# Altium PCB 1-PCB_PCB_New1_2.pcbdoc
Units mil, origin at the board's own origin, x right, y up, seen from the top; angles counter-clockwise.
Board outline 6537.83 x 6002.81 mil, 2 copper layers (Top Layer, Bottom Layer); 93 components, 94 nets, 408 pads, 132 vias.
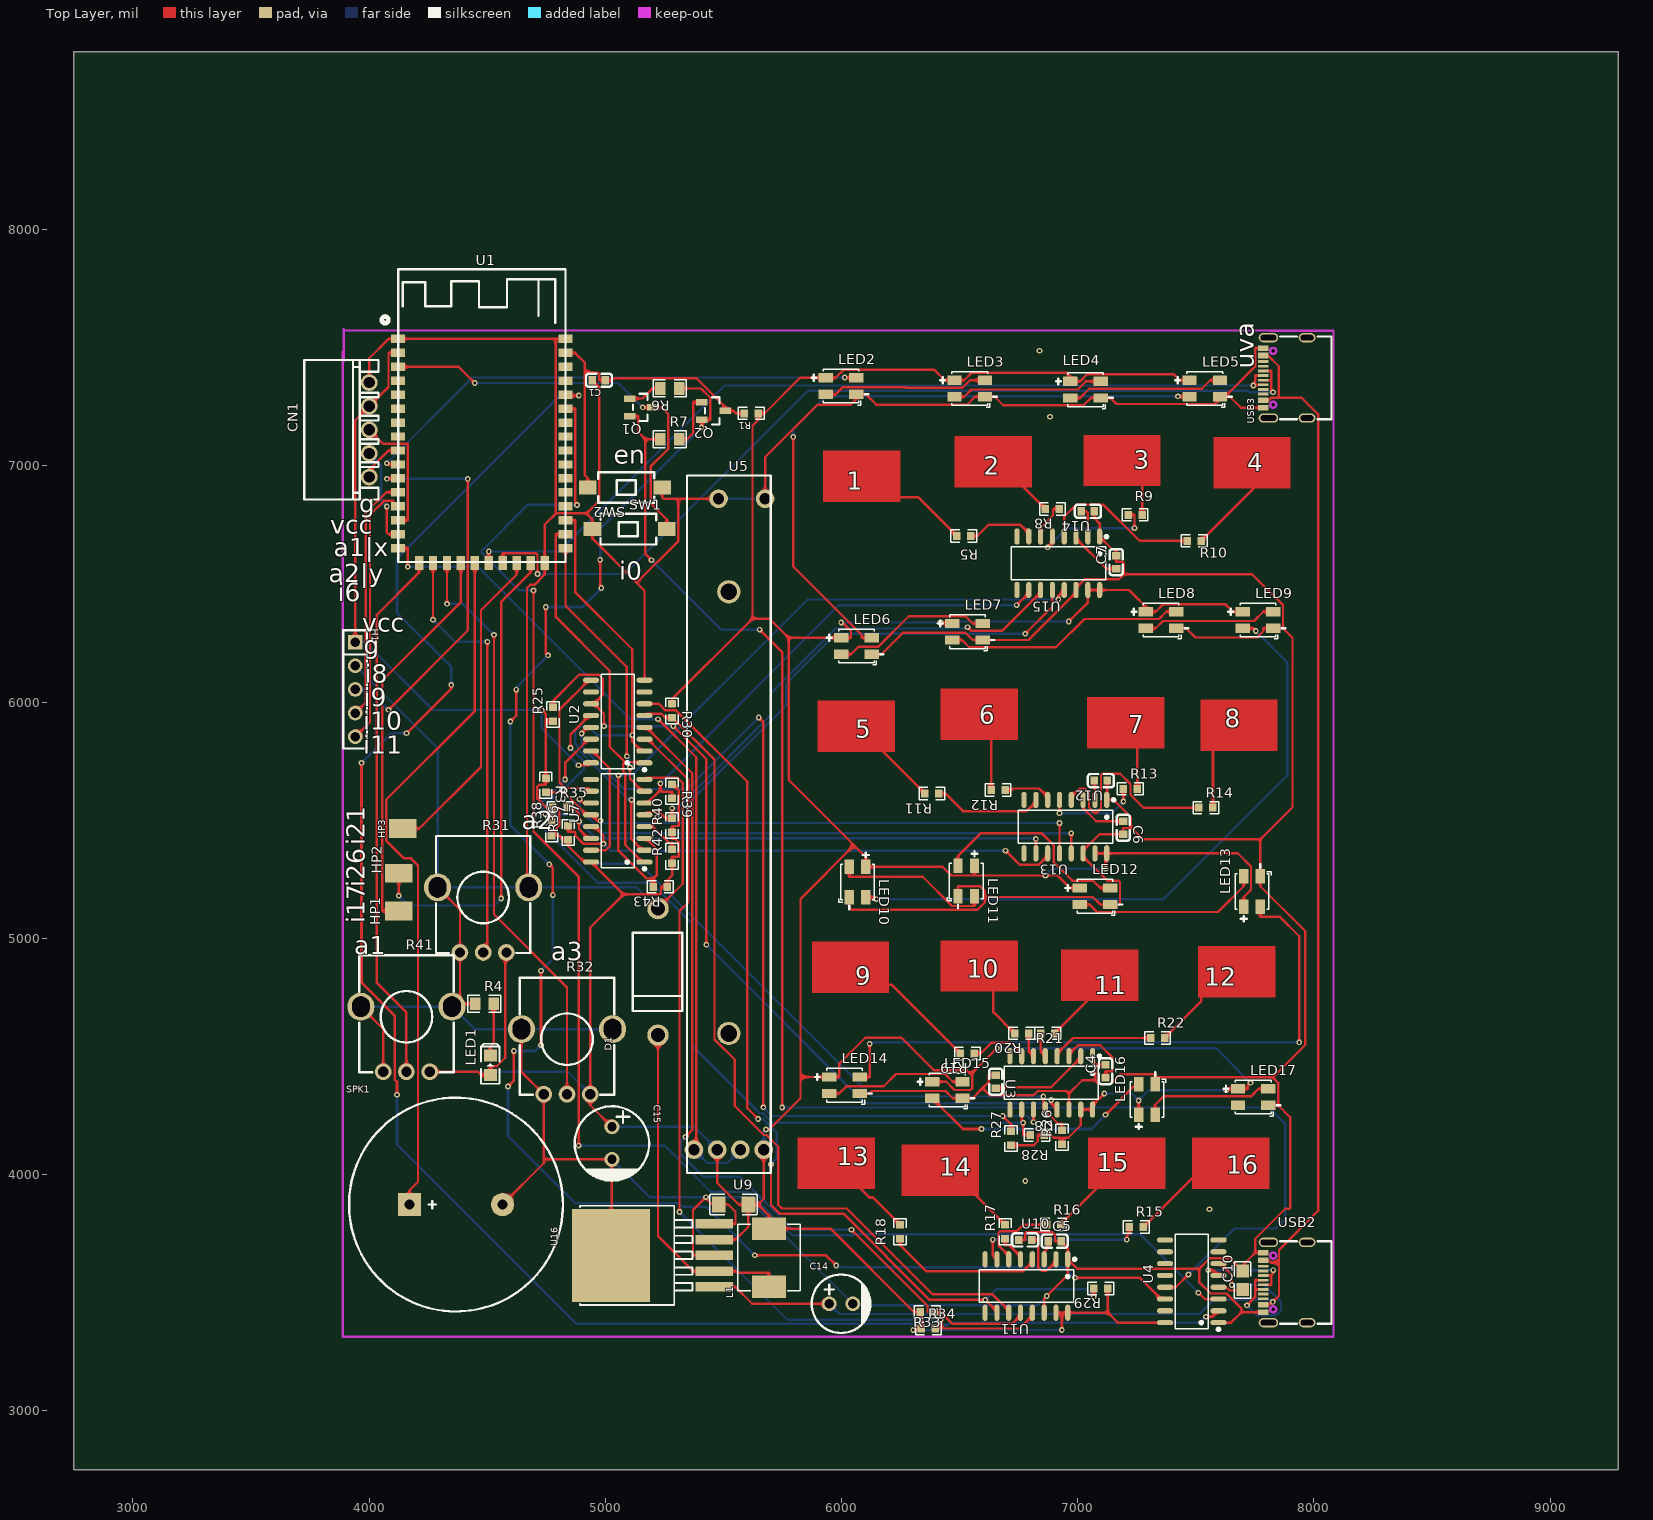
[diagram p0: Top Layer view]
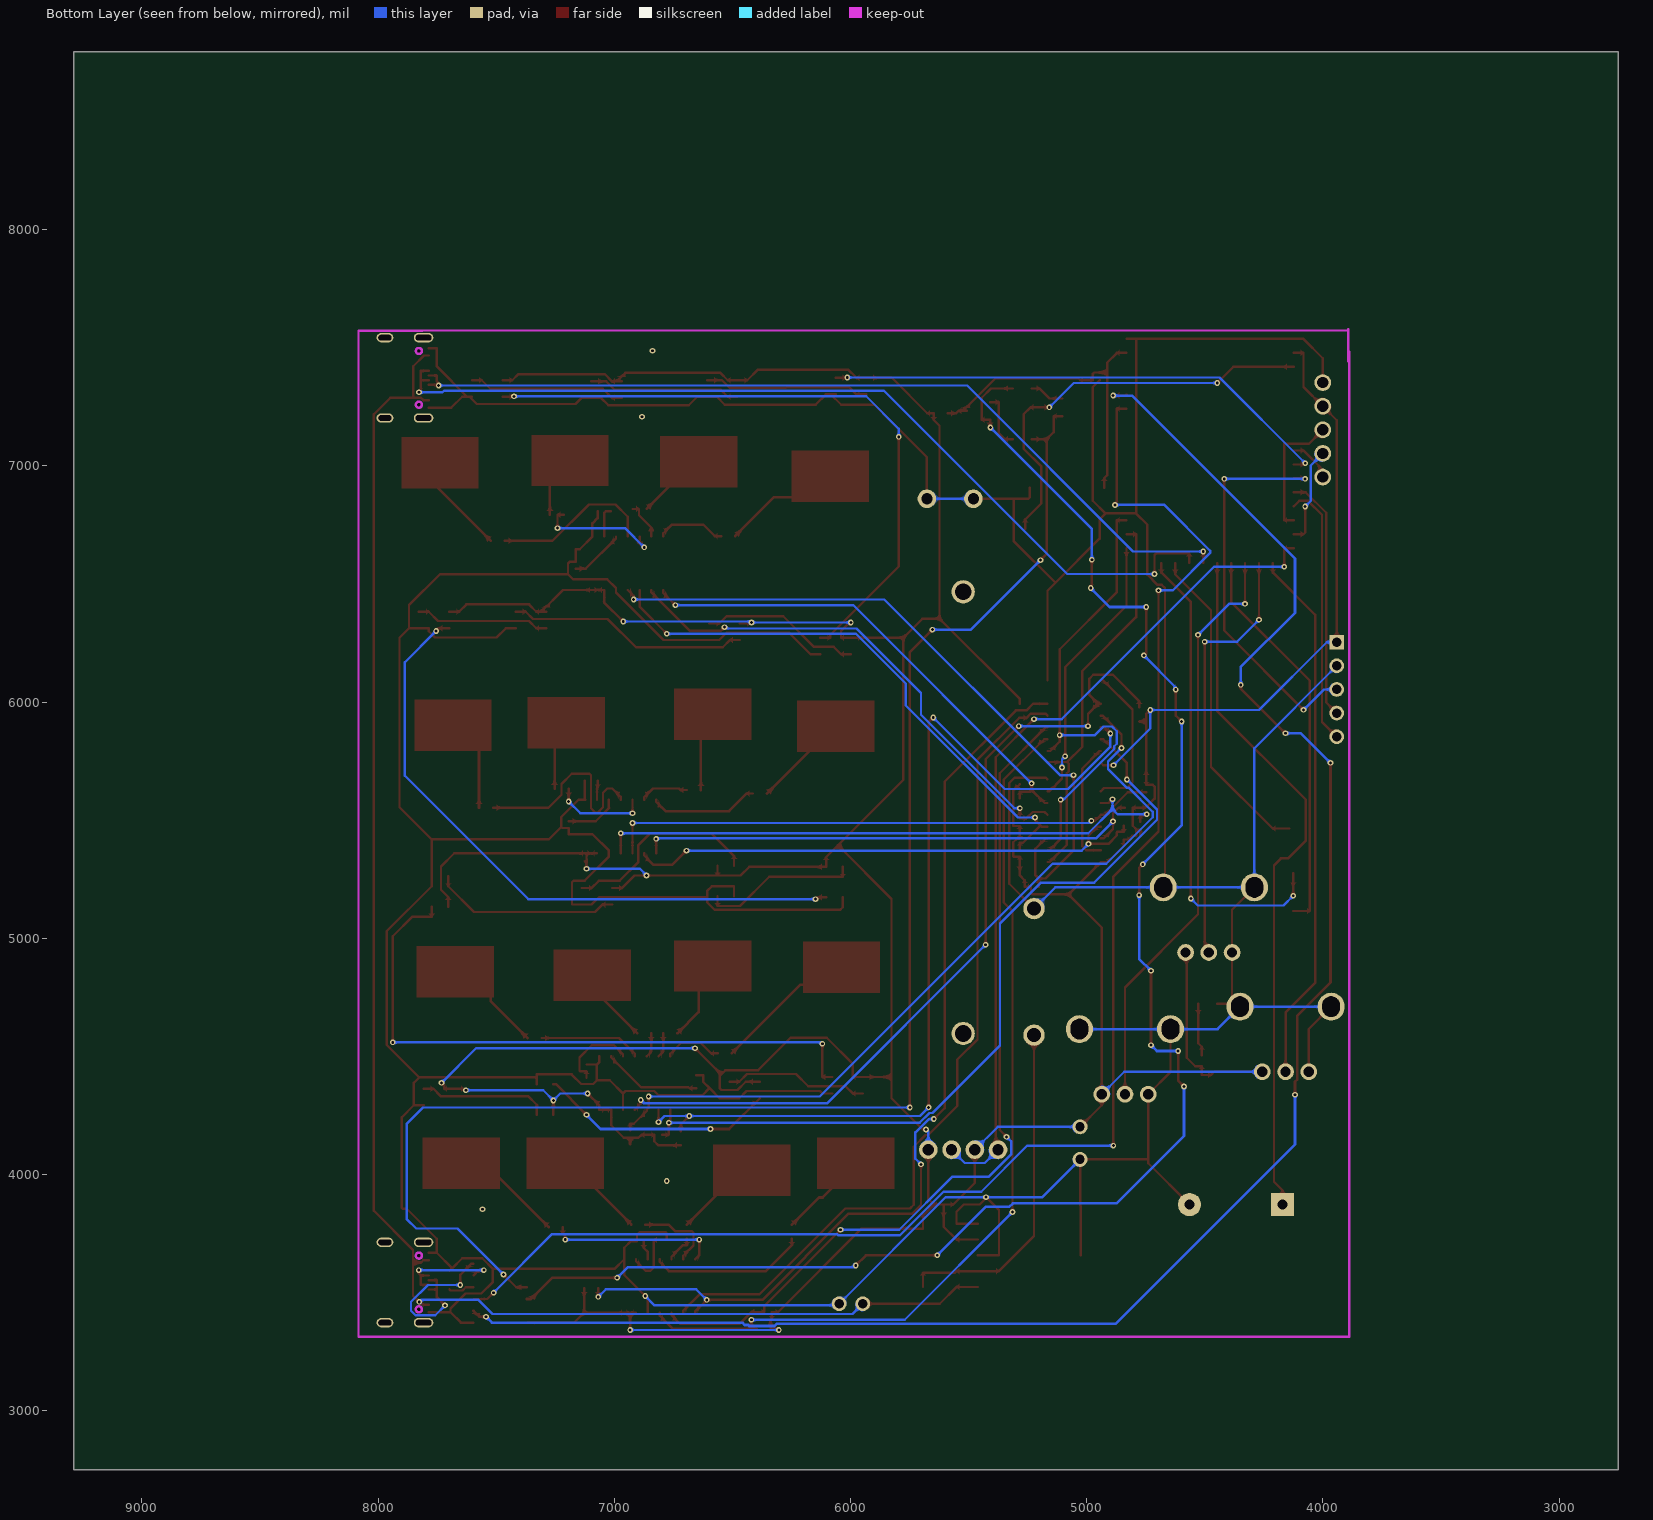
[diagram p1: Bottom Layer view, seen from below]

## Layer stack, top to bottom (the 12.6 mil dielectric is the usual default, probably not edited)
Top Layer: signal copper (thickness not stored)
Dielectric: dielectric 12.6, FR-4, Dk 4.8
Bottom Layer: signal copper (thickness not stored)

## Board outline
9287.83,2750 2750,2750 2750,8752.81 9287.83,8752.81

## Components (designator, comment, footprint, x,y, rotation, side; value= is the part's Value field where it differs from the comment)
C1 "CL10A105KB8NNNC" C0603 4972.83,7362.81 r180 top
C4 "30pF" C0603 7117.83,4437.81 r90 top
C5 "30pF" C0603 6902.83,3717.81 r0 top
C6 "30pF" C0603 7192.83,5467.81 r270 top
C7 "30pF" C0603 7162.83,6592.81 r90 top
C10 "1uF" C0805 7697.83,3552.81 r90 top
C14 "SHW680UF10V6.3X11" CAP-TH_BD6.3-P2.50-D1.0-FD 5997.83,3452.81 r0 top
C15 "KNH2220UF35V149EC0049" CAP-TH_BD8.0-P3.50-D0.6-FD-2 5027.83,4132.81 r270 top
CN1 "5264-5AWD" CONN-TH_5P-P2.50_5264-5AWD 3972.83,7152.81 r90 top
D1 "1N5824_C7503125" DO-27_BD5.3-L8.4-P12.40-D1.3-RD 5222.83,4857.81 r90 top
H1 "HDR-F_2.54_1x5P" HDR-TH_5P-P2.54-V-F 3941.16,6053.58 r270 top
HP1 "焊盘" 焊盘 4125.52,5115.47 r90 top
HP2 "焊盘" 焊盘 4125.52,5275.47 r90 top
HP3 "焊盘" 焊盘 4142.1,5464.83 r90 top
L1 "FXL0630-330-M" IND-SMD_L7.0-W6.6_FXL0630 5692.83,3647.81 r90 top
LED1 "LED-0805_G" LED0805_GREEN 4512.83,4462.81 r90 top
LED2 "WS2812B-MINI" LED-SMD_4P-L3.5-W3.5-TL_WS2812B 5997.83,7337.81 r0 top
LED3 "WS2812B-MINI" LED-SMD_4P-L3.5-W3.5-TL_WS2812B 6542.83,7327.81 r0 top
LED4 "WS2812B-MINI" LED-SMD_4P-L3.5-W3.5-TL_WS2812B 7032.83,7322.81 r0 top
LED5 "WS2812B-MINI" LED-SMD_4P-L3.5-W3.5-TL_WS2812B 7537.83,7327.81 r0 top
LED6 "WS2812B-MINI" LED-SMD_4P-L3.5-W3.5-TL_WS2812B 6062.83,6237.81 r0 top
LED7 "WS2812B-MINI" LED-SMD_4P-L3.5-W3.5-TL_WS2812B 6532.83,6297.81 r0 top
LED8 "WS2812B-MINI" LED-SMD_4P-L3.5-W3.5-TL_WS2812B 7352.83,6347.81 r0 top
LED9 "WS2812B-MINI" LED-SMD_4P-L3.5-W3.5-TL_WS2812B 7762.83,6347.81 r0 top
LED10 "WS2812B-MINI" LED-SMD_4P-L3.5-W3.5-TL_WS2812B 6067.83,5237.81 r270 top
LED11 "WS2812B-MINI" LED-SMD_4P-L3.5-W3.5-TL_WS2812B 6527.83,5242.81 r270 top
LED12 "WS2812B-MINI" LED-SMD_4P-L3.5-W3.5-TL_WS2812B 7072.83,5177.81 r0 top
LED13 "WS2812B-MINI" LED-SMD_4P-L3.5-W3.5-TL_WS2812B 7737.83,5197.81 r90 top
LED14 "WS2812B-MINI" LED-SMD_4P-L3.5-W3.5-TL_WS2812B 6012.83,4377.81 r0 top
LED15 "WS2812B-MINI" LED-SMD_4P-L3.5-W3.5-TL_WS2812B 6447.83,4357.81 r0 top
LED16 "WS2812B-MINI" LED-SMD_4P-L3.5-W3.5-TL_WS2812B 7292.83,4317.81 r90 top
LED17 "WS2812B-MINI" LED-SMD_4P-L3.5-W3.5-TL_WS2812B 7742.83,4327.81 r0 top
Q1 "S8050" SOT-23-3_L2.9-W1.3-P1.90-LS2.4-BR 5152.83,7247.81 r180 top
Q2 "S8050" SOT-23-3_L2.9-W1.3-P1.90-LS2.4-BR 5457.83,7232.81 r180 top
R1 "0603WAF1002T5E" R0603 5617.83,7222.81 r180 top
R4 "1kΩ" R0805 4487.83,4722.81 r0 top
R5 "1kΩ" R0603 6517.83,6702.81 r180 top
R6 "10kΩ" R0805 5272.83,7327.81 r180 top
R7 "10kΩ" R0805 5272.83,7112.81 r0 top
R8 "1kΩ" R0603 6892.83,6817.81 r180 top
R9 "1kΩ" R0603 7242.83,6792.81 r0 top
R10 "1kΩ" R0603 7492.83,6682.81 r0 top
R11 "1kΩ" R0603 6382.83,5612.81 r180 top
R12 "1kΩ" R0603 6662.83,5627.81 r180 top
R13 "1kΩ" R0603 7222.83,5632.81 r0 top
R14 "1kΩ" R0603 7542.83,5552.81 r0 top
R15 "1kΩ" R0603 7247.83,3777.81 r0 top
R16 "1kΩ" R0603 6897.83,3787.81 r0 top
R17 "1kΩ" R0603 6692.83,3757.81 r90 top
R18 "1kΩ" R0603 6247.83,3757.81 r90 top
R19 "1kΩ" R0603 6532.83,4512.81 r180 top
R20 "1kΩ" R0603 6762.83,4597.81 r180 top
R21 "1kΩ" R0603 6872.83,4597.81 r0 top
R22 "1kΩ" R0603 7337.83,4577.81 r0 top
R25 "1kΩ" R0603 4777.83,5947.81 r90 top
R26 "1kΩ" R0603 6932.83,4157.81 r90 top
R27 "1kΩ" R0603 6717.83,4152.81 r90 top
R28 "1kΩ" R0603 6827.83,4167.81 r180 top
R29 "1kΩ" R0603 7097.83,3517.81 r180 top
R30 "1kΩ" R0603 5282.83,5962.81 r270 top
R31 "10kΩ" RES-ADJ-TH_RK09K1130AJ3 4482.83,5077.81 r0 top
R32 "10kΩ" RES-ADJ-TH_RK09K1130AJ3 4837.83,4477.81 r0 top
R33 "1kΩ" R0603 6362.83,3417.81 r0 top
R34 "1kΩ" R0603 6367.83,3347.81 r0 top
R35 "1kΩ" R0603 4807.83,5552.81 r0 top
R36 "1kΩ" R0603 4842.83,5447.81 r90 top
R37 "1kΩ" R0603 4747.83,5647.81 r270 top
R38 "1kΩ" R0603 4772.83,5462.81 r90 top
R39 "1kΩ" R0603 5282.83,5622.81 r270 top
R40 "1kΩ" R0603 5282.83,5477.81 r90 top
R41 "10kΩ" RES-ADJ-TH_RK09K1130AJ3 4157.83,4572.81 r0 top
R42 "1kΩ" R0603 5282.83,5347.81 r90 top
R43 "1kΩ" R0603 5232.83,5217.81 r180 top
SPK1 "GSPK2307P-8R1W" SPK-TH_BD23.0-P10.00-D0.8-L-RD 4367.83,3872.81 r0 top
SW1 "TS-1101-C-W" SW-SMD_L6.0-W3.3-LS8.0 5102.83,6732.81 r0 top
SW2 "TS-1101-C-W" SW-SMD_L6.0-W3.3-LS8.0 5082.83,6907.81 r180 top
U1 "ESP32S2" ESP32S2 4122.83,7537.81 r0 top
U2 "SN74HC165DR" SOP-16_L10.0-W3.9-P1.27-LS6.0-BL 5052.83,5917.81 r90 top
U3 "4.7nF" C0603 6652.83,4392.81 r270 top
U4 "CH340C" SOP-16_L10.0-W3.9-P1.27-LS6.0-BL 7482.83,3547.81 r90 top
U5 "B10K滑动电位器" B10K 5522.83,5482.81 r0 top
U7 "SN74HC165DR" SOP-16_L10.0-W3.9-P1.27-LS6.0-BL 5052.83,5497.81 r90 top
U8 "SC04B_C5337815" SOP-16_L10.0-W3.9-P1.27-LS6.0-BL 6887.83,4387.81 r180 top
U9 "10uF" C1206 5542.83,3872.81 r0 top
U10 "4.7nF" C0603 6777.83,3722.81 r0 top
U11 "SC04B_C5337815" SOP-16_L10.0-W3.9-P1.27-LS6.0-BL 6782.83,3527.81 r180 top
U12 "4.7nF" C0603 7097.83,5667.81 r180 top
U13 "SC04B_C5337815" SOP-16_L10.0-W3.9-P1.27-LS6.0-BL 6947.83,5472.81 r180 top
U14 "4.7nF" C0603 7042.83,6807.81 r180 top
U15 "SC04B_C5337815" SOP-16_L10.0-W3.9-P1.27-LS6.0-BL 6917.83,6587.81 r180 top
U16 "LM2596S-3.3" TO-263-5_L10.0-W8.4-P1.70-LS15.3-BR 5242.83,3657.81 r0 top
USB2 "TYPE-C16PIN" USB-C-SMD_TYPE-C16PIN 7877.83,3542.81 r90 top
USB3 "TYPE-C16PIN" USB-C-SMD_TYPE-C16PIN 7877.83,7372.81 r90 top

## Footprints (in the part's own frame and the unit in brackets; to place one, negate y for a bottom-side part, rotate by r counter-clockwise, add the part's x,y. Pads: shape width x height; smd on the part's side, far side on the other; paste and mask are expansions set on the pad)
B10K [mm]
  round 2 hole 1.2 copper offset 0,0: 1a(-1.25,-35) 1b(3.75,-35)
  round 2 hole 1.2: 2a(-3.75,-35) 2b(1.25,-35) 3a(-1.102,35) 3b(3.898,35)
  round 2.5 hole 1.8: 9(0,25) 10(0,-22.5)
  silkscreen extent -4.5,-37.5 4.5,37.5
C0603 [mm]
  rect 0.8x0.9 smd: 1(-0.7,0) 2(0.7,0)
  silkscreen extent -1.41,-0.71 1.39,0.72
C0805 [mm]
  rect 1.41x1.35 smd: 1(-1,0) 2(1,0)
  silkscreen extent -1.96,-0.9 1.96,0.9
C1206 [mm]
  rect 1.485x1.728 smd: 1(-1.593,0) 2(1.593,0)
  silkscreen extent -2.56,-1.09 2.56,1.09
CAP-TH_BD6.3-P2.50-D1.0-FD [mm]
  round 1.6 hole 1: 1(-1.27,0) 2(1.27,0)
  silkscreen extent -3.15,-3.15 3.17,3.15
CAP-TH_BD8.0-P3.50-D0.6-FD-2 [mm]
  round 1.6 hole 1: 1(-1.75,0) 2(1.75,0)
  silkscreen extent -3.96,-4 4.04,4
CONN-TH_5P-P2.50_5264-5AWD [mm]
  round 1.8 hole 1.2: 1(-5.08,-0.7) 2(-2.54,-0.7) 3(0,-0.7) 4(2.54,-0.7) 5(5.08,-0.7)
  silkscreen extent -7.5,-1.7 7.5,6.3
DO-27_BD5.3-L8.4-P12.40-D1.3-RD [mm]
  round 2.3 hole 1.5: 1(-6.8,0) 2(6.8,0)
  silkscreen extent -4.2,-2.6 4.2,2.7
ESP32S2 [mm]
  rect 1.5x0.9 smd: 1(0,-0.006) 2(0,-1.505) 3(0,-3.006) 4(0,-4.505) 5(0,-6.006) 6(0,-7.505) 7(0,-9.006) 8(0,-10.505) 9(0,-12.006) 10(0,-13.505) 11(0,-15.006) 12(0,-16.505) 13(0,-18.006) 14(0,-19.505) 15(0,-21.006) 16(0,-22.505) 27(18,-22.505) 28(18,-21.006) 29(18,-19.505) 30(18,-18.006) 31(18,-16.505) 32(18,-15.006) 33(18,-13.505) 34(18,-12.006) 35(18,-10.505) 36(18,-9.006) 37(18,-7.505) 38(18,-6.006) 39(18,-4.505) 40(18,-3.006) 41(18,-1.505) 42(18,-0.006)
  rect 0.9x1.5 smd: 17(2.25,-24.1) 18(3.75,-24.1) 19(5.25,-24.1) 20(6.75,-24.1) 21(8.25,-24.1) 22(9.75,-24.1) 23(11.25,-24.1) 24(12.75,-24.1) 25(14.25,-24.1) 26(15.75,-24.1)
  silkscreen extent -1.76,-24 18,7.5
HDR-TH_5P-P2.54-V-F [mil]
  rect 62x62 hole 40.16: 1(-200,0)
  round 62 hole 40.16: 2(-100,0) 3(0,0) 4(100,0) 5(200,0)
  silkscreen extent -250,-50 250,50
IND-SMD_L7.0-W6.6_FXL0630 [mm]
  rect 2.424x3.62 smd: 1(3.128,0) 2(-3.128,0)
  silkscreen extent -3.58,-3.38 3.58,3.38
LED0805_GREEN [mil]
  rect 51.2x55.1 smd: 1(-41.35,0) 2(41.35,0)
  silkscreen extent -79,-39 91,39
LED-SMD_4P-L3.5-W3.5-TL_WS2812B [mm]
  rect 1.545x0.997 smd: 1(-1.638,0.89) 2(-1.638,-0.89) 3(1.638,-0.89) 4(1.638,0.89)
  silkscreen extent -3.17,-2.04 2.92,1.82
R0603 [mil]
  rect 31.75x34.02 smd: 1(-29.66,0) 2(29.66,0)
  silkscreen extent -55,-26 55,26
R0805 [mm]
  rect 1.133x1.377 smd: 1(-1,0) 2(1,0)
  silkscreen extent -1.76,-0.92 1.76,0.92
RES-ADJ-TH_RK09K1130AJ3 [mm]
  round 1.8 hole 1.1: 1(-2.5,-3.5) 2(0,-3.5) 3(2.5,-3.5)
  oval 2.9x3 hole 1.9 slot 2.2 at 90 deg copper offset 0,0: 4(-4.9,3.5) 5(4.9,3.5)
  silkscreen extent -5.08,-3.56 5.08,9.02
SOP-16_L10.0-W3.9-P1.27-LS6.0-BL [mm]
  oval 0.56x1.745 smd: 1(-4.445,-2.872) 2(-3.175,-2.872) 3(-1.905,-2.872) 4(-0.635,-2.872) 5(0.635,-2.872) 6(1.905,-2.872) 7(3.175,-2.872) 8(4.445,-2.872) 9(4.445,2.872) 10(3.175,2.872) 11(1.905,2.872) 12(0.635,2.872) 13(-0.635,2.872) 14(-1.905,2.872) 15(-3.175,2.872) 16(-4.445,2.872)
  silkscreen extent -5.33,-3.02 5.08,1.77
SOT-23-3_L2.9-W1.3-P1.90-LS2.4-BR [mm]
  rect 1.25x0.7 smd: 1(1.25,-0.95) 2(1.25,0.95) 3(-1.25,0)
  silkscreen extent -0.65,-1.46 0.9,1.46
SPK-TH_BD23.0-P10.00-D0.8-L-RD [mm]
  rect 2.5x2.5 hole 1.1: 1(-5,0)
  round 2.5 hole 1.1: 2(5,0)
  silkscreen extent -11.5,-11.5 11.5,11.5
SW-SMD_L6.0-W3.3-LS8.0 [mm]
  rect 1.9x1.5 smd: 1(-4,0) 2(4,0)
  silkscreen extent -3.14,-1.67 2.86,1.63
TO-263-5_L10.0-W8.4-P1.70-LS15.3-BR [mm]
  rect 4x1.02 smd: 1(5.55,-3.4) 2(5.55,-1.7) 3(5.55,0) 4(5.55,1.7) 5(5.55,3.4)
  rect 8.4x10 smd: 6(-5.55,0)
  silkscreen extent -8.91,-5.33 3.2,5.33
USB-C-SMD_TYPE-C16PIN [mm]
  oval 1x2.1 hole 0.6 slot 1.7 at 90 deg: 1(-4.32,1.787) 2(4.32,1.787)
  oval 1x1.8 hole 0.6 slot 1.4 at 90 deg: 3(-4.32,-2.362) 4(4.32,-2.362)
  rect 0.6x1.15 smd: A1B12(-3.2,2.362) A4B9(-2.4,2.362) B1A12(3.2,2.362) B4A9(2.4,2.362)
  rect 0.3x1.15 smd: A5(-1.25,2.362) A6(-0.25,2.362) A7(0.25,2.362) A8(-1.75,2.362) B5(1.75,2.362) B6(0.75,2.362) B7(-0.75,2.362) B8(1.25,2.362)
  Multi-Layer board cut-out: 2.89,0.963 3.05,1.009 3.166,1.127 3.209,1.288 3.166,1.449 3.05,1.567 2.89,1.613 2.89,1.613 2.73,1.567 2.614,1.449 2.571,1.288 2.614,1.127 2.73,1.009 2.89,0.963
  Multi-Layer board cut-out: -2.89,0.963 -2.73,1.009 -2.614,1.127 -2.571,1.288 -2.614,1.449 -2.73,1.567 -2.89,1.613 -2.89,1.613 -3.05,1.567 -3.166,1.449 -3.209,1.288 -3.166,1.127 -3.05,1.009 -2.89,0.963
  silkscreen extent -4.45,-5 4.45,0.52
焊盘 [mm]
  rect 2x3 smd: 1(0,0)

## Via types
v1: diameter 24, hole 12, Top Layer to Bottom Layer, 103 vias
v2: diameter 24.02, hole 12.01, Top Layer to Bottom Layer, 29 vias

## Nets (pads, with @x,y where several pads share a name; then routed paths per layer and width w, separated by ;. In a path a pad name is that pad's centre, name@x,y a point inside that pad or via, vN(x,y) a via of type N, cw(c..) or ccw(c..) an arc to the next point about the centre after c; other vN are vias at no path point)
$1N3: C10.1 U4.4 | length 109.4
  Top Layer w10: U4.4 7628.43,3522.81 7642.23,3509.01 7693.43,3509.01 C10.1
$1N11: LED4.2 LED5.4 | length 665.1
  Top Layer w10: LED4.2@6968.33,7287.81 7009.93,7287.81 7049.13,7327.01 7525.03,7327.01 7560.73,7362.81 LED5.4@7602.33,7362.81
$1N12: LED2.2 LED3.4 | length 701
  Top Layer w10: LED2.2@5933.33,7302.81 5974.93,7302.81 6005.63,7333.61 6272.03,7333.61 6274.63,7331.01 6512.33,7331.01 6544.13,7362.81 LED3.4@6607.33,7362.81
$1N29: LED5.2 LED6.4 | length 2781.3
  Top Layer w10: v1(5795.53,7122.91) 5795.53,6573.81 6085.73,6283.51 6085.73,6272.81 LED6.4@6127.33,6272.81 ; v1(7424.23,7294.51) 7430.03,7294.51 7431.73,7292.81 LED5.2@7473.33,7292.81
  Bottom Layer w10: v1(5795.53,7122.91) 5795.53,7156.81 5933.23,7294.51 v1(7424.23,7294.51)
$1N30: LED7.2 LED8.4 | length 1024.3
  Top Layer w10: LED7.2@6468.33,6262.81 6509.93,6262.81 6540.63,6232.01 6908.03,6232.01 7028.03,6352.01 7343.73,6352.01 7374.53,6382.81 LED8.4@7417.33,6382.81
$1N31: LED6.2 LED7.4 | length 678.4
  Top Layer w10: LED6.2@5998.33,6202.81 6039.93,6202.81 6070.63,6233.61 6154.73,6233.61 6284.73,6363.61 6525.03,6363.61 6555.73,6332.81 LED7.4@6597.33,6332.81
$1N32: LED8.2 LED9.4 | length 568
  Top Layer w10: LED8.2@7288.33,6312.81 7329.93,6312.81 7360.63,6343.61 7746.53,6343.61 7785.73,6382.81 LED9.4@7827.33,6382.81
$1N33: LED9.2 LED10.4 | length 2731.7
  Top Layer w10: LED10.4@6102.83,5173.31 6140.13,5173.31 v1(6147.73,5165.71) ; LED9.2@7698.33,6312.81 7742.63,6312.81 v1(7754.13,6301.31)
  Bottom Layer w10: v1(6147.73,5165.71) 7363.83,5165.71 7886.53,5688.31 7886.53,6169.01 v1(7754.13,6301.31)
$1N34: LED10.2 LED11.4 | length 664.6
  Top Layer w10: LED10.2 6032.83,5260.71 6343.73,5260.71 6467.73,5136.71 6562.83,5136.71 LED11.4@6562.83,5178.31
$1N35: LED11.2 LED12.4 | length 863.7
  Top Layer w10: LED11.2 6492.83,5348.91 6588.23,5444.31 6848.43,5444.31 6897.83,5394.91 6897.83,5323.01 6977.23,5243.61 7065.03,5243.61 7095.73,5212.81 LED12.4@7137.33,5212.81
$1N36: LED12.2 LED13.4 | length 794.2
  Top Layer w10: LED12.2@7008.33,5142.81 7049.93,5142.81 7081.13,5111.61 7593.63,5111.61 7702.83,5220.71 LED13.4
$1N46: LED3.2 LED4.4 | length 646
  Top Layer w10: LED3.2@6478.33,7292.81 6519.93,7292.81 6550.63,7323.61 6999.93,7323.61 7034.13,7357.81 LED4.4@7097.33,7357.81
$1N47: LED2.4 U1.10 | length 2188.7
  Top Layer w10: v1(4074.83,7011.41) 4080.03,7006.11 U1.10 ; v1(6013.73,7374.41) 6015.43,7372.81 LED2.4@6062.33,7372.81
  Bottom Layer w10: v1(4074.83,7011.41) 4437.83,7374.41 v1(6013.73,7374.41)
$1N48: LED13.2 LED14.4 | length 2693.7
  Top Layer w10: LED14.4@6077.33,4412.81 6118.93,4412.81 v1(6118.93,4553.81) ; LED13.2@7772.83,5133.31 7772.83,5091.71 7854.43,5091.71 7937.73,5008.51 v1(7937.73,4559.51)
  Bottom Layer w10: v1(6118.93,4553.81) 6124.63,4559.51 v1(7937.73,4559.51)
$1N49: LED14.2 LED15.4 | length 611.7
  Top Layer w10: LED14.2@5948.33,4342.81 5989.93,4342.81 6020.63,4373.61 6178.93,4373.61 6230.63,4425.31 6438.23,4425.31 6470.73,4392.81 LED15.4@6512.33,4392.81
$1N50: LED15.2 LED16.4 | length 1006.7
  Top Layer w11.02: LED15.2 6513.32,4192.81 v2(6592.83,4192.81) ; v2(7117.83,4252.81) 7247.3,4382.28 LED16.4
  Bottom Layer w11.02: v2(6592.83,4192.81) 7057.83,4192.81 v2(7117.83,4252.81)
$1N51: LED16.2 LED17.4 | length 549.2
  Top Layer w10: LED16.2@7327.83,4253.31 7327.83,4294.91 7365.03,4332.01 7735.03,4332.01 7765.73,4362.81 LED17.4@7807.33,4362.81
$1N61: CN1.1 U1.9 | length 186.8
  Top Layer w10: CN1.1 4000.43,6983.41 4082.13,7065.11 U1.9@4122.83,7065.11
$1N66: R25.2 U2.11 U8.13 | length 3608.1
  Top Layer w10: R25.2 4777.83,6004.61 4888.73,6115.51 4972.03,6115.51 4988.53,6099.01 4988.53,6030.51 U2.11@4950.83,5992.81 ; U2.11 U2.11@4950.83,5992.81 ; v1(4994.13,5898.21) 4994.13,5949.61 U2.11@4950.83,5992.81 ; v1(5287.83,5898.21) 5427.83,5758.21 v1(5427.83,4972.81) ; v1(6887.83,4315.21) 6887.83,4299.71 U8.13
  Bottom Layer w10: v1(4994.13,5898.21) v1(5287.83,5898.21) ; v1(5427.83,4972.81) 6099.63,4301.01 6873.63,4301.01 v1(6887.83,4315.21)
$1N67: R26.2 U2.12 U8.12 | length 3385.5
  Top Layer w10: v1(4852.73,5806.01) 4852.73,5863.11 4932.43,5942.81 U2.12 ; v1(6854.63,4330.11) 6854.63,4282.91 U8.12 6862.83,4269.01 6917.33,4214.61 6932.83,4214.61 R26.2
  Bottom Layer w10: v1(4852.73,5806.01) 4909.83,5748.81 4909.83,5716.81 4830.83,5637.91 4823.13,5637.91 4720.33,5535.11 4720.33,5512.31 4916.83,5315.81 5144.03,5315.81 6129.83,4330.11 v1(6854.63,4330.11)
$1N68: R27.2 U2.13 U8.11 | length 4016.9
  Top Layer w10: v1(4899.53,5867.31) 4925.03,5892.81 U2.13 ; v1(5649.83,5934.61) 5669.03,5915.41 v1(5669.03,4284.11) ; v1(6682.73,4247.51) 6717.83,4212.51 R27.2 ; v1(6812.83,4221.71) U8.11
  Bottom Layer w10: v1(4899.53,5867.31) 4899.73,5867.21 4899.73,5811.81 5079.53,5632.01 5347.13,5632.01 v1(5649.83,5934.61) ; v1(5669.03,4284.11) 5705.63,4247.51 v1(6682.73,4247.51) 6786.93,4247.51 v1(6812.83,4221.71)
$1N69: R28.2 U2.14 U8.10 | length 3482.8
  Top Layer w10: v1(4829.63,5672.61) 4829.63,5742.81 4929.63,5842.81 U2.14 ; U8.10 6762.83,4224.91 v1(6768.73,4219.11) 6768.73,4170.21 6771.03,4167.81 R28.2@6798.13,4167.81
  Bottom Layer w10: v1(4829.63,5672.61) 4702.13,5545.11 4702.13,5502.01 4968.23,5235.81 5193.63,5235.81 5366.73,5062.71 5366.73,4546.71 5652.83,4260.61 5665.83,4260.61 5707.43,4219.11 v1(6768.73,4219.11)
$1N71: R22.1 U8.4 | length 433.1
  Top Layer w10: U8.4 6912.83,4511.11 6979.53,4577.81 R22.1@7308.13,4577.81
$1N72: R21.1 U8.5 | length 105.1
  Top Layer w10: R21.1@6843.13,4597.81 6843.13,4520.61 U8.5
$1N73: R20.1 U8.6 | length 105.3
  Top Layer w10: R20.1 6792.53,4521.21 U8.6
$1N74: R19.1 U8.7 | length 248.6
  Top Layer w10: R19.1 6589.63,4512.81 6634.63,4557.91 6716.13,4557.91 6762.83,4511.11 U8.7
$1N75: R15.1 U11.7 | length 716.3
  Top Layer w10: v1(6639.93,3724.21) 6639.93,3658.81 U11.7 ; v1(7207.43,3724.21) 7207.43,3739.01 7218.13,3749.61 R15.1@7218.13,3777.81
  Bottom Layer w10: v1(6639.93,3724.21) v1(7207.43,3724.21)
$1N76: R16.1 U11.6 | length 347.9
  Top Layer w10: U11.6 6707.83,3656.01 6664.63,3699.21 6664.63,3753.01 6672.03,3760.41 6742.73,3760.41 6770.13,3787.81 R16.1@6868.13,3787.81
$1N77: R17.1 U11.5 | length 123.5
  Top Layer w10: R17.1@6692.83,3728.11 6692.83,3701.01 6708.83,3701.01 6757.83,3652.01 U11.5
$1N78: R18.1 U11.4 | length 659.7
  Top Layer w10: R18.1@6247.83,3728.11 6247.83,3701.01 6357.83,3591.01 6768.93,3591.01 6807.83,3630.01 U11.4
$1N79: R29.2 U2.6 U11.10 | length 4114.4
  Top Layer w10: U2.6 5226.83,5992.81 5254.83,5964.81 5299.83,5964.81 5601.13,5663.51 5601.13,4281.11 v1(5647.03,4235.21) ; v1(5701.13,4042.81) 5701.13,3870.41 5737.33,3834.21 6007.73,3834.21 6372.73,3469.11 v1(6608.13,3469.11) 6657.83,3419.41 U11.10 ; v1(7068.13,3481.81) R29.2@7068.13,3517.81
  Bottom Layer w10: v1(5647.03,4235.21) 5668.13,4235.21 5725.23,4178.11 5725.23,4067.01 v1(5701.13,4042.81) ; v1(6608.13,3469.11) 6652.63,3513.71 7036.33,3513.71 v1(7068.13,3481.81)
$1N81: R30.2 U2.5 U11.11 | length 3554.1
  Top Layer w10: U2.5 5174.23,5951.11 5236.73,5951.11 5254.63,5933.11 5282.83,5933.11 5285.63,5933.11 5462.43,5756.31 5462.43,4572.01 5547.83,4486.61 5547.83,4289.91 5670.73,4167.11 5682.43,4167.11 5731.83,4117.71 5731.83,3871.91 5747.33,3856.31 6022.23,3856.31 6386.23,3492.31 6639.13,3492.31 6707.83,3423.61 U11.11
$1N82: R33.2 U2.4 U11.12 | length 3691.2
  Top Layer w10: U2.4 5173.63,5892.81 5368.03,5698.41 5368.03,4188.31 v1(5339.13,4159.41) ; v1(6041.93,3766.01) 6365.43,3442.51 6365.43,3417.81 R33.2 6419.63,3417.81 6470.03,3367.41 6720.53,3367.41 6757.83,3404.71 U11.12
  Bottom Layer w10: v1(5339.13,4159.41) 5320.03,4140.41 5320.03,4084.41 5413.63,3990.91 5568.43,3990.91 5793.23,3766.01 v1(6041.93,3766.01)
$1N85: R34.2 U2.3 U11.13 | length 3878.2
  Top Layer w10: U2.3 5179.83,5842.81 5350.73,5671.91 5350.73,5152.01 5314.03,5115.31 v1(5314.03,3841.21) ; R34.2 6419.63,3347.81 ; v1(6419.63,3384.71) 6419.63,3347.81 ; U11.13 6807.83,3402.51 6753.13,3347.81 6419.63,3347.81
  Bottom Layer w10: v1(5314.03,3841.21) 5770.53,3384.71 v1(6419.63,3384.71)
$1N90: R11.1 U13.7 | length 465.1
  Top Layer w10: R11.1 6439.63,5612.81 6513.83,5538.61 6783.13,5538.61 6822.83,5578.31 U13.7
$1N91: R12.1 U13.6 | length 210.2
  Top Layer w10: R12.1 6719.63,5627.81 6726.23,5634.41 6836.43,5634.41 6872.83,5598.11 U13.6
$1N92: R13.1 U13.5 | length 401
  Top Layer w10: v1(6922.83,5529.51) U13.5 ; v1(7193.13,5579.01) R13.1@7193.13,5632.81
  Bottom Layer w10: v1(6922.83,5529.51) 7143.63,5529.51 v1(7193.13,5579.01)
$1N93: R14.1 U13.4 | length 883.5
  Top Layer w10: U13.4 6972.83,5598.51 7008.83,5634.41 7029.33,5634.41 7047.83,5615.91 7047.83,5554.51 7071.43,5530.91 7079.03,5530.91 7098.53,5550.41 7098.53,5690.11 7105.13,5696.71 7180.13,5696.71 7223.43,5653.41 7223.43,5607.61 7278.23,5552.81 R14.1@7513.13,5552.81
$1N94: R35.2 U7.14 U13.10 | length 2221.2
  Top Layer w10: R35.2 4864.63,5552.81 4888.53,5528.91 v1(4888.53,5494.91) 4888.53,5462.41 4928.13,5422.81 U7.14 ; U13.10 v1(6822.83,5420.91)
  Bottom Layer w10: v1(4888.53,5494.91) 4960.53,5422.91 6820.93,5422.91 v1(6822.83,5420.91)
$1N96: R36.2 U7.13 U13.11 | length 2251.1
  Top Layer w10: R36.2 4842.83,5450.41 4869.93,5450.41 4872.43,5447.91 4872.43,5435.21 4908.03,5399.61 v1(4992.03,5399.61) 4992.03,5434.21 4953.43,5472.81 U7.13 ; v1(6694.53,5371.21) 6755.03,5310.71 6833.33,5310.71 6872.83,5350.31 U13.11
  Bottom Layer w10: v1(4992.03,5399.61) 5020.43,5371.21 v1(6694.53,5371.21)
$1N97: R37.2 U7.12 U13.12 | length 2357.4
  Top Layer w10: R37.2@4747.83,5618.11 4826.23,5618.11 4921.53,5522.81 U7.12 4964.73,5497.81 v1(4979.93,5497.81) ; U13.12 v1(6922.83,5488.41)
  Bottom Layer w10: v1(4979.93,5497.81) 4989.33,5488.41 v1(6922.83,5488.41)
$1N100: R38.2 U7.11 U13.13 | length 2517.4
  Top Layer w10: v1(4745.43,5525.41) 4751.33,5519.61 4772.83,5519.61 R38.2 ; v1(4890.63,5588.41) 4906.23,5572.81 U7.11 ; U13.13 v1(6972.83,5444.41)
  Bottom Layer w10: v1(4745.43,5525.41) 4868.83,5525.41 4890.63,5547.31 ; v1(4890.63,5588.41) 4890.63,5547.31 ; v1(6972.83,5444.41) 4993.53,5444.41 4890.63,5547.31
$1N102: R5.1 U15.7 | length 294.6
  Top Layer w10: R5.1 6574.63,6702.81 6623.33,6751.51 6756.23,6751.51 6792.83,6714.91 U15.7
$1N103: R8.1 U15.6 | length 165.8
  Top Layer w10: U15.6 6842.83,6738.11 6895.43,6790.71 6895.43,6817.81 R8.1
$1N104: R9.1 U15.5 | length 538.5
  Top Layer w10: v1(6872.93,6655.01) 6892.83,6675.01 U15.5 ; R9.1@7213.13,6792.81 7240.23,6792.81 v1(7240.23,6736.61)
  Bottom Layer w10: v1(6872.93,6655.01) 6954.43,6736.61 v1(7240.23,6736.61)
$1N105: R10.1 U15.4 | length 689.3
  Top Layer w10: U15.4 6942.83,6784.61 6994.93,6836.71 7107.33,6836.71 7261.23,6682.81 R10.1@7463.13,6682.81
$1N106: R39.2 U7.6 U15.10 | length 2104.3
  Top Layer w10: U7.6 5177.83,5572.81 5233.13,5628.01 ; v1(5233.13,5655.81) 5233.13,5628.01 ; R39.2@5282.83,5593.11 5282.83,5620.21 5240.93,5620.21 5233.13,5628.01 ; v1(6741.43,6410.41) 6792.83,6461.91 U15.10
  Bottom Layer w10: v1(5233.13,5655.81) 5987.73,6410.41 v1(6741.43,6410.41)
$1N108: R40.2 U7.5 U15.11 | length 2192.9
  Top Layer w10: U7.5 5177.93,5534.81 5228.13,5534.81 5254.63,5508.31 5254.63,5507.51 R40.2 v1(5282.83,5550.51) ; v1(6533.53,6317.51) 6549.53,6301.61 6680.03,6301.61 6842.83,6464.31 U15.11
  Bottom Layer w10: v1(5282.83,5550.51) 5305.93,5550.51 5701.63,5946.11 5701.63,6038.71 5974.73,6311.81 6527.83,6311.81 v1(6533.53,6317.51)
$1N109: R42.2 U7.4 U15.12 | length 2388.1
  Top Layer w10: U7.4 5190.63,5472.81 U7.4@5195.83,5478.11 ; v1(5218.53,5511.61) 5218.53,5500.81 U7.4@5195.83,5478.11 ; R42.2 5282.83,5404.61 5269.33,5404.61 U7.4@5195.83,5478.11 ; v1(6777.63,6289.31) 6892.83,6404.51 U15.12
  Bottom Layer w10: v1(5218.53,5511.61) 5291.23,5511.61 5765.73,5986.11 5765.73,6078.51 5976.53,6289.31 v1(6777.63,6289.31)
$1N112: R43.2 U7.3 U15.13 | length 2973.9
  Top Layer w10: v1(5055.43,5690.71) 5055.43,5371.31 5173.63,5253.11 5203.13,5253.11 ; U7.3 5173.33,5422.81 5217.43,5378.71 5217.43,5267.41 5203.13,5253.11 ; R43.2@5203.13,5217.81 5203.13,5253.11 ; v1(6917.93,6434.21) 6917.93,6449.81 U15.13
  Bottom Layer w10: v1(5055.43,5690.71) 5113.13,5690.71 5856.63,6434.21 v1(6917.93,6434.21)
$1N114: U2.9 U7.10 | length 642.7
  Top Layer w10: U7.10 4926.33,5636.21 4829.53,5636.21 4806.03,5659.71 4806.03,5968.01 4930.83,6092.81 U2.9
$1N2096: Q2.1 R7.2 | length 237.9
  Top Layer w10: R7.2 5345.73,7112.81 5372.83,7140.01 5372.83,7270.21 Q2.1
$1N2099: Q1.1 R6.2 | length 147.4
  Top Layer w10: Q1.1 5157.33,7285.21 5199.93,7327.81 R6.2@5233.43,7327.81
$1N2166: LED1.2 R4.2 | length 224.6
  Top Layer w10: LED1.2 4512.83,4541.01 4527.23,4555.41 R4.2
$1N2213: C4.1 U8.3 | length 343.2
  Top Layer w10: U8.3 6962.83,4508.61 7001.73,4547.51 7095.43,4547.51 7147.33,4495.71 7147.33,4439.71 7144.73,4437.11 7117.83,4437.11 C4.1@7117.83,4410.21
$1N2214: U3.2 U8.2 | length 419.3
  Top Layer w10: U3.2@6652.83,4365.21 6681.73,4365.21 6686.13,4369.71 6886.83,4369.71 7012.83,4495.61 U8.2
$1N2215: U10.2 U11.2 | length 249.4
  Top Layer w10: U10.2 6832.33,3722.81 6832.33,3607.01 6846.83,3592.41 6868.03,3592.41 6907.83,3632.31 U11.2
$1N2218: C5.1 U11.3 | length 84.1
  Top Layer w10: U11.3 6857.83,3671.51 6875.23,3688.91 C5.1@6875.23,3717.81
$1N2223: U12.2 U13.2 | length 83
  Top Layer w10: U12.2@7070.23,5667.81 7070.23,5638.91 7072.83,5636.31 U13.2
$1N2226: C6.1 U13.3 | length 227.8
  Top Layer w10: U13.3 7022.83,5551.21 7078.63,5495.41 C6.1
$1N2231: U14.2 U15.2 | length 130.2
  Top Layer w10: U14.2@7015.23,6807.81 7035.43,6807.81 7042.83,6800.41 U15.2
$1N2234: C7.1 U15.3 | length 230.8
  Top Layer w10: U15.3 6992.83,6693.11 7120.73,6565.21 C7.1@7162.83,6565.21
$1N5140: D1.1 L1.2 U16.2 | length 1444.1
  Top Layer w10: D1.1 5222.83,3739.51 5371.43,3590.91 U16.2 5551.23,3590.91 5558.53,3583.61 5692.83,3583.61 L1.2
$1N5379: U2.15 U7.15 | length 525.1
  Top Layer w10: U7.15 5001.63,5372.81 5019.03,5390.21 5019.03,5718.91 4945.13,5792.81 U2.15
$1N5430: CN1.3 U1.14 | length 552.1
  Top Layer w10: CN1.3 4059.23,7094.01 4163.23,7094.01 4163.53,7093.71 4163.53,6769.91 U1.14
$1N5439: CN1.2 U1.15 | length 416.5
  Top Layer w10: v1(4074.93,6828.11) 4074.93,6718.01 4082.13,6710.81 U1.15
  Bottom Layer w10: CN1.2 4051.63,7001.61 4051.63,6851.41 v1(4074.93,6828.11)
$1N5456: U1.16 U5.2a U5.2b | length 3583.5
  Top Layer w10: U1.16 4163.53,6651.81 v1(4163.53,6572.91) ; v1(5223.33,5927.91) 5384.63,5766.61 5384.63,4114.21 U5.2a
  Bottom Layer w10: v1(4163.53,6572.91) 4460.83,6572.91 5105.83,5927.91 v1(5223.33,5927.91) ; U5.2a 5431.13,4048.91 5516.13,4048.91 U5.2b
$1N5500: HP1.1 U1.20 | length 1681.9
  Top Layer w10: HP1.1 4055.23,5115.51 4055.23,6091.11 4388.63,6424.41 U1.20
$1N5779: HP3.1 U1.24 | length 1365.3
  Top Layer w10: HP3.1 4212.43,5464.81 4473.33,5725.81 4473.33,6388.51 4624.83,6540.01 U1.24
$1N5793: HP2.1 U1.25 | length 2030.4
  Top Layer w10: v1(4125.53,5180.41) HP2.1 ; v1(4558.93,5168.21) 4558.93,6423.41 4683.83,6548.31 U1.25
  Bottom Layer w10: v1(4125.53,5180.41) 4167.03,5138.91 4529.63,5138.91 v1(4558.93,5168.21)
$1N6036: SPK1.1 U1.21 | length 2960.1
  Top Layer w10: SPK1.1@4170.93,3872.81 4170.93,3933.21 4207.03,3969.31 4207.03,5308.81 4177.63,5338.21 4148.23,5338.21 4071.83,5414.51 4071.83,5586.61 4447.63,5962.31 U1.21
ADC1: R41.2 U1.17 | length 2279.7
  Top Layer w10: R41.2 4157.83,4685.61 4032.93,4810.51 4032.93,6369.81 4211.43,6548.31 U1.17
ADC2: R31.2 U1.18 | length 1832.2
  Top Layer w10: v1(4270.43,6348.61) U1.18@4270.43,6589.01 ; R31.2 4500.63,4957.81 v1(4500.63,6255.81)
  Bottom Layer w10: v1(4270.43,6348.61) 4363.23,6255.81 v1(4500.63,6255.81)
ADC3: R32.2 U1.19 | length 2499.3
  Top Layer w10: v1(4329.53,6415.71) U1.19 ; v1(4528.53,6284.51) 4528.53,5101.61 4837.83,4792.31 R32.2
  Bottom Layer w10: v1(4329.53,6415.71) 4397.33,6415.71 v1(4528.53,6284.51)
CLK: U1.29 U2.2 U7.2 | length 2048
  Top Layer w10: U1.29 4872.23,6769.91 4872.23,6466.31 5114.33,6224.11 v1(5114.33,5860.11) 5114.33,5832.61 5154.13,5792.81 U2.2 ; v1(5110.13,5586.71) 5110.13,5420.41 5157.83,5372.81 U7.2
  Bottom Layer w10: v1(5110.13,5586.71) 5098.33,5586.71 4883.53,5801.51 4883.53,5813.21 4872.73,5824.01 4872.73,5876.41 4892.73,5896.41 4928.83,5896.41 4965.23,5860.11 v1(5114.33,5860.11)
CLKINH: U1.30
D+: U4.5 USB2.A6 USB2.B6 | length 461.3
  Top Layer w10: v1(7552.23,3595.01) 7573.73,3595.01 U4.5 ; USB2.A6 7818.63,3533.01 7818.63,3572.31 ; USB2.B6 7818.63,3572.31 ; v1(7827.43,3595.01) 7827.43,3581.11 7818.63,3572.31
  Bottom Layer w10: v1(7552.23,3595.01) v1(7827.43,3595.01)
D-: U4.6 USB2.A7 USB2.B7 | length 752
  Top Layer w10: U4.6 7604.03,3622.81 7651.83,3575.11 v1(7651.83,3532.21) ; v1(7716.33,3445.91) 7751.03,3480.71 7751.03,3513.31 ; USB2.B7 7751.03,3513.31 ; USB2.A7@7784.83,3552.61 7751.03,3552.61 7751.03,3513.31
  Bottom Layer w10: v1(7651.83,3532.21) 7789.23,3532.21 7860.33,3461.11 7860.33,3423.31 7841.33,3404.31 7757.93,3404.31 v1(7716.33,3445.91)
DTR: Q1.2 R7.1 U4.13 | length 6564.7
  Top Layer w10: Q1.2 5139.43,7210.41 5139.43,7143.11 5169.73,7112.81 ; v1(5195.73,6601.11) 5169.73,6627.21 5169.73,7112.81 ; R7.1@5233.43,7112.81 5169.73,7112.81 ; v1(5653.13,6306.91) 5748.33,6211.61 v1(5748.33,4283.61) ; U4.13 7414.83,3522.81 v1(7468.83,3576.81)
  Bottom Layer w10: v1(5195.73,6601.11) 5489.93,6306.91 v1(5653.13,6306.91) ; v1(5748.33,4283.61) 7809.43,4283.61 7879.03,4214.01 7879.03,3811.91 7838.13,3771.11 7663.13,3771.11 v1(7468.83,3576.81)
EN: C1.1 Q2.3 R1.2 SW2.2 U1.41 | length 1420.9
  Top Layer w10: U1.41 4872.23,7478.51 4912.83,7437.81 4912.83,7395.71 ; SW2.2@4925.33,6907.81 4925.33,6948.51 4912.83,6960.91 4912.83,7395.71 ; Q2.3 Q2.3@5524.93,7232.81 ; R1.2@5588.13,7222.81 5552.83,7222.81 5542.83,7232.81 Q2.3@5524.93,7232.81 ; 4912.83,7395.71 4967.53,7395.71 4973.53,7389.71 4973.53,7362.81 C1.1 5027.33,7362.81 5035.73,7371.21 5386.53,7371.21 Q2.3@5524.93,7232.81
GND: C1.2 C4.2 C5.2 C6.2 C7.2 C10.2 C14.2 C15.2 CN1.5 D1.2 H1.2 LED2.3 LED3.3 LED4.3 LED5.3 LED6.3 LED7.3 LED8.3 LED9.3 LED10.3 LED11.3 LED12.3 LED13.3 LED14.3 LED15.3 LED16.3 LED17.3 R4.1 R31.1 R31.4 R31.5 R32.1 R32.4 R32.5 R41.1 R41.4 R41.5 SPK1.2 SW1.1 SW2.1 U1.1 U1.26 U1.42 U2.8 U3.1 U4.1 U5.3a U5.3b U7.8 U8.1 U8.14 U9.1 U10.1 U11.1 U11.14 U12.1 U13.1 U13.14 U14.1 U15.1 U15.14 U16.3 U16.5 U16.6 USB2.A1B12 USB2.B1A12 USB3.A1B12 USB3.B1A12 | length 30764.2
  Top Layer w10: R41.4 4059.43,4616.11 R41.1 ; CN1.5 4000.43,7455.91 4082.13,7537.61 U1.1 4790.83,7537.61 ; R31.4 4384.43,5121.11 R31.1 R41.5@4384.43,4722.81 ; R41.5 4372.23,4710.61 R41.5@4384.43,4722.81 ; R4.1@4448.43,4722.81 R41.5@4384.43,4722.81 ; SPK1.2@4564.63,3872.81 4739.43,4047.61 4739.43,4063.91 ; R32.4 4644.93,4434.51 R32.1 4739.43,4063.91 ; R31.5 4668.63,5222.71 4668.63,6482.51 4682.23,6496.11 4699.53,6496.11 4742.93,6539.61 U1.26 4742.93,6750.81 4790.83,6798.81 ; U1.42 4790.83,7537.61 ; C1.2@4945.23,7362.81 4973.93,7334.11 4973.93,6852.61 4920.03,6798.81 ; U16.6 5024.33,3865.91 5027.83,3869.41 C15.2 4739.43,4063.91 ; U7.8 5172.73,5679.61 5305.43,5679.61 5328.03,5657.11 5328.03,5230.71 D1.2 ; U2.8 5165.93,6471.51 5132.43,6505.01 ; SW2.1 5240.33,6867.11 5246.63,6860.81 5309.43,6860.81 ; U16.3 5371.43,3657.81 5371.43,3849.41 v1(5426.23,3904.21) 5426.23,3899.21 5452.73,3872.81 U9.1 5520.53,3872.81 5551.23,3842.11 5551.23,3791.71 U16.5 ; U5.3a@5479.43,6860.81 5309.43,6860.81 ; U5.3b 5676.33,7036.41 5898.63,7258.81 6039.13,7258.81 LED2.3@6083.13,7302.81 ; LED10.3 6032.83,5131.71 6044.13,5120.41 6574.43,5120.41 6606.93,5152.91 6606.93,5174.81 ; LED2.3 LED2.3@6083.13,7302.81 ; LED14.3 6118.93,4342.81 6129.63,4353.61 6440.03,4353.61 6470.73,4322.81 LED15.3 6553.93,4322.81 6596.93,4365.81 ; LED6.3 6168.93,6202.81 6259.63,6293.61 6525.03,6293.61 6555.73,6262.81 LED7.3 6791.63,6262.81 6992.83,6464.01 U15.14 6992.83,6482.61 7030.43,6520.31 7174.53,6520.31 7195.83,6541.61 ; LED11.3 6492.83,5219.71 6493.03,5219.91 6587.03,5219.91 6606.93,5200.01 6606.93,5174.81 ; U3.1 6623.93,4420.41 6623.93,4392.91 6596.93,4365.81 ; U10.1@6750.23,3722.81 6777.13,3722.81 6777.13,3749.71 6782.43,3755.01 6893.23,3755.01 6903.53,3744.71 6903.53,3717.81 C5.2@6929.83,3717.81 ; U11.14 6857.83,3474.41 v1(6869.13,3485.61) 6957.83,3574.41 U11.1 ; C5.2 C5.2@6929.83,3717.81 ; U8.14 6962.83,4342.81 ; U8.1 7062.83,4476.31 7073.73,4465.41 ; U14.1 7070.43,6778.91 7092.83,6756.51 U15.1 7146.43,6647.31 7162.83,6647.31 C7.2 7162.83,6593.51 7189.73,6593.51 7195.83,6587.41 7195.83,6541.61 ; C4.2 7073.73,4465.41 ; U13.1 7124.13,5587.21 U13.1@7125.43,5587.21 ; U12.1 U13.1@7125.43,5587.21 ; LED16.3@7327.83,4382.31 LED16.3@7327.83,4404.91 ; LED8.3 7458.93,6312.81 7498.03,6273.71 7759.33,6273.71 7785.73,6300.11 7785.73,6312.81 LED9.3 7868.93,6312.81 ; U4.1 7649.33,3372.81 7693.33,3416.81 ; LED5.3 LED5.3@7612.73,7292.81 ; C10.2 C10.2@7686.43,3603.61 ; USB2.A1B12 7693.33,3416.81 ; USB2.B1A12 7751.63,3668.81 ; USB3.A1B12 7689.93,7246.81 7643.93,7292.81 LED5.3@7623.13,7292.81 ; USB3.B1A12 7751.03,7498.81 7751.03,7420.71 LED5.3@7623.13,7292.81 ; LED17.3 7848.93,4292.81 ; 4790.83,6798.81 4920.03,6798.81 ; 4790.83,6798.81 4790.83,7537.61 ; 4920.03,6798.81 4945.33,6773.51 4945.33,6732.81 4945.33,6692.11 5132.43,6505.01 ; 5132.43,6505.01 5309.43,6682.01 5309.43,6860.81 ; LED2.3@6083.13,7302.81 6103.93,7302.81 6147.43,7259.21 6532.23,7259.21 6565.73,7292.81 LED3.3 6648.93,7292.81 6684.63,7257.01 7025.03,7257.01 7055.73,7287.81 LED4.3 7138.93,7287.81 7164.63,7262.01 7581.93,7262.01 LED5.3@7612.73,7292.81 ; 6596.93,4365.81 6626.93,4335.81 6813.03,4335.81 6830.73,4353.51 6952.13,4353.51 6962.83,4342.81 ; 6606.93,5174.81 7063.83,5174.81 7095.73,5142.81 LED12.3 7178.93,5142.81 7178.93,5237.21 7172.53,5243.61 7125.43,5243.61 7022.83,5346.21 U13.14 7022.83,5371.11 7091.93,5440.21 7192.83,5440.21 7192.83,5467.11 7219.73,5467.11 7224.43,5471.81 ; C5.2@6929.83,3717.81 6957.83,3689.81 U11.1 ; U11.1 6998.43,3600.31 7513.83,3600.31 ; 6962.83,4342.81 7018.83,4398.81 7073.73,4398.81 ; 7073.73,4398.81 7073.73,4465.41 ; 7073.73,4398.81 7089.33,4383.11 7139.93,4383.11 7180.73,4423.91 7327.83,4423.91 LED16.3@7327.83,4404.91 ; U13.1@7125.43,5587.21 7150.33,5587.21 7224.43,5513.11 7224.43,5471.81 ; 7195.83,6541.61 7737.93,6541.61 7868.93,6410.61 7868.93,6312.81 ; 7224.43,5471.81 7277.73,5418.61 7772.83,5418.61 ; LED16.3@7327.83,4404.91 7334.03,4411.11 7825.73,4411.11 ; 7513.83,3600.31 7558.73,3645.31 7643.93,3645.31 7685.53,3603.61 C10.2@7686.43,3603.61 ; 7513.83,3600.31 7513.83,3545.51 7563.03,3496.31 7630.23,3496.31 7693.33,3433.21 7693.33,3416.81 ; LED5.3@7612.73,7292.81 LED5.3@7623.13,7292.81 ; C10.2@7686.43,3603.61 7751.63,3668.81 ; 7751.63,3668.81 7751.63,3728.01 7878.63,3855.01 7896.13,3855.01 7899.03,3857.91 7899.03,4242.71 7848.93,4292.81 ; 7772.83,5418.61 7909.03,5554.71 7909.03,6272.71 7868.93,6312.81 ; 7772.83,5418.61 7772.83,5262.31 7772.83,5220.71 7963.73,5029.91 7963.73,4549.11 7825.73,4411.11 ; 7825.73,4411.11 7848.93,4387.91 7848.93,4292.81
  Bottom Layer w10: H1.2@3941.13,6153.61 4289.93,5804.81 R31.4 R31.5 5132.73,5215.61 D1.2 ; R41.4 R41.5 4445.73,4615.61 R32.4 R32.5 ; C15.2 5187.53,3904.21 v1(5426.23,3904.21) 5596.43,3904.21 C14.2 6054.63,3446.01 6829.43,3446.01 v1(6869.13,3485.61) ; U5.3a@5479.43,6860.81 U5.3b
  other v2: 7557.83,3852.81 6777.83,3972.81 6882.83,7207.81 6837.83,7487.81
IO0: Q1.3 SW1.2 U1.3 | length 1772.8
  Top Layer w10: U1.3 4378.93,7419.51 v1(4447.33,7351.21) ; v1(5158.23,7247.81) Q1.3 5237.83,7247.81 5266.93,7218.71 5266.93,7072.81 5191.73,6997.71 5191.73,6842.01 5260.33,6773.51 SW1.2
  Bottom Layer w10: v1(4447.33,7351.21) 5054.93,7351.21 v1(5158.23,7247.81)
IO8: H1.3 U1.11 | length 1685.1
  Top Layer w10: v1(4074.93,6945.11) 4080.23,6945.11 4082.13,6947.01 U1.11 ; v1(4081.63,5967.21) 4417.83,6303.31 v1(4417.83,6945.11)
  Bottom Layer w10: H1.3@3941.13,6053.61 3995.23,6053.61 v1(4081.63,5967.21) ; v1(4074.93,6945.11) v1(4417.83,6945.11)
IO9: H1.4 U1.12 | length 1039.2
  Top Layer w10: H1.4@3941.13,5953.61 3986.03,5998.51 3986.03,6801.71 4072.33,6888.01 U1.12
IO10: H1.5 U1.13 | length 1118.3
  Top Layer w10: H1.5@3941.13,5853.61 4003.83,5916.31 4003.83,6793.11 4062.53,6851.81 4099.93,6851.81 U1.13
LD: U1.28 U2.1 U7.1 | length 1679.6
  Top Layer w10: U1.28 4790.83,6710.81 4790.83,6359.91 5019.03,6131.71 5019.03,5810.11 5082.73,5746.41 ; U7.1 5157.03,5322.81 5083.83,5396.01 5083.83,5699.01 5075.93,5706.81 5075.93,5739.61 5082.73,5746.41 ; U2.1 5162.33,5746.41 5082.73,5746.41
OUT: U1.27 U7.7 | length 1172.4
  Top Layer w10: U1.27 4831.53,6407.71 5090.73,6148.41 5090.73,5771.51 v1(5091.33,5771.01) ; v1(5104.53,5723.21) 5104.53,5675.91 5157.53,5622.81 U7.7
  Bottom Layer w10: v1(5091.33,5771.01) 5104.53,5757.81 v1(5104.53,5723.21)
RTS: Q2.2 R6.1 U4.14 | length 7014.9
  Top Layer w10: v2(4762.83,5312.81) 4777.83,5297.81 v2(4777.83,5182.81) ; R6.1 5405.23,7327.81 5444.43,7288.61 5444.43,7195.41 Q2.2
  Top Layer w11.02: v2(4587.83,4372.81) 4612.83,4397.81 v2(4612.83,4522.81) ; v2(4597.83,5917.81) 4622.83,5942.81 v2(4622.83,6052.81) ; v2(4727.83,4547.81) v2(4727.83,4862.81) ; v2(4747.83,6402.81) 4747.83,6207.81 v2(4757.83,6197.81) ; v2(4977.83,6602.81) 4977.83,6487.81 v2(4982.83,6482.81) ; v2(5407.83,7162.81) 5408.63,7163.61 Q2.2 ; v2(5632.83,3657.81) 5934.82,3657.81 v2(5977.83,3614.8) ; v2(6987.83,3562.81) 7262.83,3562.81 7352.83,3472.81 U4.14
  Bottom Layer w11.02: v2(4587.83,4372.81) 4587.83,4162.81 4872.83,3877.81 5312.83,3877.81 5327.83,3862.81 5427.83,3862.81 v2(5632.83,3657.81) ; v2(4597.83,5917.81) 4597.83,5477.81 v2(4762.83,5312.81) ; v2(4612.83,4522.81) 4702.83,4522.81 v2(4727.83,4547.81) ; v2(4622.83,6052.81) 4622.83,6062.81 v2(4757.83,6197.81) ; v2(4727.83,4862.81) 4777.83,4912.81 v2(4777.83,5182.81) ; v2(4747.83,6402.81) 4902.83,6402.81 v2(4982.83,6482.81) ; v2(4977.83,6602.81) 4977.83,6732.81 v2(5407.83,7162.81) ; v2@5982.83,3607.81 6942.83,3607.81 v2(6987.83,3562.81)
RX: U1.38 U4.2 | length 7770
  Top Layer w11.02: v2(3967.83,5742.81) 3967.83,4812.81 4107.83,4672.81 4107.83,4402.81 4117.83,4392.81 v2(4117.83,4337.81) ; v2(4157.83,5867.81) 4347.83,6057.81 v2(4347.83,6072.81) ; U1.38 4835.05,7297.81 v2(4887.83,7297.81) ; v2(7542.83,3397.81) 7570.92,3397.81 U4.2
  Bottom Layer w11.02: v2(3967.83,5742.81) 4092.83,5867.81 v2(4157.83,5867.81) ; v2(4117.83,4337.81) 4117.83,4127.81 4877.83,3367.81 6312.83,3367.81 6322.23,3358.41 6428.43,3358.41 6432.83,3362.81 6447.83,3362.81 6457.83,3372.81 7517.83,3372.81 v2(7542.83,3397.81) ; v2(4347.83,6072.81) 4347.83,6147.81 4117.83,6377.81 4117.83,6607.81 4807.83,7297.81 v2(4887.83,7297.81)
TX: U1.37 U4.3 | length 6640.3
  Top Layer w10: v1(4696.13,6472.91) 4696.13,5451.91 4887.03,5261.01 v1(4887.03,4122.11) ; U1.37 4872.23,7242.31 4872.23,6842.81 v1(4880.23,6834.81) ; v1(7510.93,3499.61) 7537.73,3472.81 U4.3
  Bottom Layer w10: v1(4696.13,6472.91) 4635.73,6472.91 4477.43,6631.21 4477.43,6641.11 4671.13,6834.81 v1(4880.23,6834.81) ; v1(4887.03,4122.11) 5251.43,4122.11 5446.33,3927.31 5606.33,3927.31 5790.83,3742.81 6051.63,3742.81 6056.13,3747.41 7263.13,3747.41 v1(7510.93,3499.61)
U+: U1.23 USB3.A6 USB3.B6 | length 3870.8
  Top Layer w10: U1.23 4565.73,6629.71 4706.13,6629.71 4712.73,6623.11 v1(4712.73,6542.11) ; USB3.A6 7818.63,7363.01 ; USB3.B6 7818.63,7402.31 7818.63,7363.01 ; v1(7826.43,7311.71) 7818.63,7319.51 7818.63,7363.01
  Bottom Layer w10: v1(4712.73,6542.11) 5081.93,6542.11 5858.03,7318.31 7720.63,7318.31 7727.23,7311.71 v1(7826.43,7311.71)
U-: U1.22 USB3.A7 USB3.B7 | length 3692.6
  Top Layer w10: U1.22 v1(4506.73,6637.61) ; v1(7743.63,7340.21) v1@7748.93,7345.41 ; USB3.B7 7751.03,7343.31 v1@7748.93,7345.41 ; USB3.A7@7784.83,7382.61 7751.03,7382.61 7751.03,7358.11 7748.93,7356.01 v1@7748.93,7345.41
  Bottom Layer w10: v1(4506.73,6637.61) 4803.33,6637.61 5505.93,7340.21 v1(7743.63,7340.21)
VBUS: C14.1 U16.1 USB2.A4B9 USB2.B4A9 USB3.A4B9 USB3.B4A9 | length 6878.8
  Top Layer w10: U16.1@5461.33,3523.91 5551.23,3523.91 5622.33,3452.81 C14.1 ; USB2.A4B9 7809.23,3448.31 7821.73,3460.81 v1(7825.93,3460.81) 7851.83,3486.71 7851.83,3627.61 ; USB2.B4A9 7808.93,3637.31 7818.53,3627.61 7851.83,3627.61 ; USB3.A4B9 7808.93,7278.31 7818.63,7288.01 7850.73,7288.01 ; USB3.B4A9 7805.53,7467.31 7850.73,7422.11 7850.73,7288.01 ; 7850.73,7288.01 7948.33,7288.01 8017.53,7218.81 8017.53,3846.51 7851.83,3680.91 7851.83,3627.61
  Bottom Layer w10: C14.1 5991.03,3409.61 7515.93,3409.61 7575.43,3469.11 7817.63,3469.11 v1(7825.93,3460.81)
VCC: C15.1 CN1.4 H1.1 L1.1 LED1.1 LED2.1 LED3.1 LED4.1 LED5.1 LED6.1 LED7.1 LED8.1 LED9.1 LED10.1 LED11.1 LED12.1 LED13.1 LED14.1 LED15.1 LED16.1 LED17.1 R1.1 R25.1 R26.1 R27.1 R28.1 R29.1 R30.1 R31.3 R32.3 R33.1 R34.1 R35.1 R36.1 R37.1 R38.1 R39.1 R40.1 R41.3 R42.1 R43.1 U1.2 U2.16 U4.16 U5.1a U5.1b U7.16 U8.15 U8.16 U9.2 U11.15 U11.16 U13.15 U13.16 U15.15 U15.16 U16.4 | length 25056
  Top Layer w10: H1.1@3941.13,6253.61 3941.13,7193.51 CN1.4 4082.13,7334.51 4082.13,7478.51 U1.2 ; R41.3 4460.63,4435.01 4474.13,4421.51 LED1.1 4512.83,4458.31 4540.43,4458.31 4576.53,4494.41 4576.53,4935.31 R31.3 ; v1(4731.03,5966.81) 4747.83,5950.01 4747.83,5918.11 ; R38.1@4772.83,5433.11 4772.83,5460.21 4789.33,5460.21 ; R25.1@4777.83,5918.11 4747.83,5918.11 ; v1(4886.63,5732.71) 4929.63,5732.71 U2.16 ; C15.1 4936.23,4293.31 R32.3 4936.23,5045.31 5076.73,5185.81 ; R39.1 5311.03,5624.31 5311.03,5476.31 5309.93,5475.21 5282.83,5475.21 5282.83,5448.11 5282.83,5421.01 5296.33,5421.01 5311.03,5406.41 5311.03,5346.31 5309.93,5345.21 5282.83,5345.21 5282.83,5318.11 5282.83,5266.31 5262.53,5246.01 R43.1 5235.43,5217.81 5235.43,5190.71 5230.53,5185.81 5076.73,5185.81 ; R30.1 5282.83,6012.91 5623.13,6353.21 ; U16.4 5551.23,3724.71 5605.53,3779.01 U9.2 ; U5.1a 5473.63,3964.31 5565.13,3872.81 U9.2 ; U5.1b@5670.43,4104.81 5670.43,3897.31 5645.93,3872.81 ; v1(5680.33,4190.31) 5693.83,4190.31 5826.43,4322.91 5826.43,4412.81 ; v1(5998.43,6336.91) 6003.63,6336.91 6039.93,6300.71 6039.93,6272.81 5998.33,6272.81 5775.83,6272.81 ; v1(6303.03,3341.91) 6305.13,3341.91 6311.03,3347.81 6338.13,3347.81 6338.13,3384.61 6333.13,3389.61 6333.13,3417.81 6306.03,3417.81 5952.83,3771.01 L1.1 5692.83,3829.91 5688.83,3829.91 5645.93,3872.81 ; LED15.1@6383.33,4392.81 6443.53,4392.81 6478.83,4357.51 6546.43,4357.51 6553.93,4365.01 6553.93,4417.01 6547.23,4423.71 ; v1(6418.93,6336.91) 6423.03,6332.81 LED7.1@6468.33,6332.81 ; LED11.1@6562.83,5307.31 6562.83,5265.91 ; v1(6658.23,4534.71) 6547.23,4423.71 ; R27.1@6717.83,4123.11 6812.83,4123.11 6830.43,4140.71 6830.43,4167.81 R28.1 6884.63,4167.81 6897.23,4155.21 6932.83,4155.21 ; U11.15 6932.83,3414.71 ; v1(6932.83,3341.91) 6932.83,3414.71 ; R26.1@6932.83,4128.11 6932.83,4155.21 ; v1(6962.03,6341.41) 7042.83,6422.21 U15.15 U15.16 7217.23,6474.71 LED8.1@7309.13,6382.81 ; LED4.1@6968.33,7357.81 LED4.1@6989.13,7357.81 ; LED12.1@7008.33,5212.81 6966.73,5212.81 6913.73,5265.91 v1(6863.43,5265.91) 6562.83,5265.91 ; U13.15 U13.16 ; v2(7112.83,4342.81) 7062.83,4292.81 U8.16 U8.15 7012.83,4208.11 6959.93,4155.21 6932.83,4155.21 ; v1(7117.53,5294.11) 7117.53,5354.41 U13.16 ; R29.1 7127.53,3414.71 ; LED16.1 v1(7257.83,4313.51) ; LED8.1@7288.33,6382.81 LED8.1@7309.13,6382.81 ; U4.16 7169.43,3372.81 7127.53,3414.71 ; LED5.1@7473.33,7362.81 7431.73,7362.81 7406.03,7388.61 7040.63,7388.61 7009.93,7357.81 LED4.1@6989.13,7357.81 ; v1(7628.33,4356.51) 7630.43,4356.51 7636.73,4362.81 7678.33,4362.81 7719.93,4362.81 7719.93,4376.21 v1(7731.63,4387.91) ; LED9.1@7698.33,6382.81 7656.73,6382.81 7626.03,6413.61 7360.63,6413.61 7329.93,6382.81 LED8.1@7309.13,6382.81 ; LED13.1 7702.83,5174.91 7733.63,5205.61 7733.63,5303.61 7677.43,5359.71 U13.16 ; 4747.83,5918.11 R37.1 4747.83,5650.41 4720.73,5650.41 4712.33,5642.01 4712.33,5591.51 4751.03,5552.81 4778.13,5552.81 4805.23,5552.81 4805.23,5476.11 4789.33,5460.21 ; 4789.33,5460.21 4789.33,5437.31 4792.23,5434.41 4806.53,5434.41 4814.63,5426.31 4814.63,5418.11 4842.83,5418.11 4842.83,5391.01 4911.03,5322.81 U7.16 5076.73,5185.81 ; U9.2 5645.93,3872.81 ; 5623.13,6353.21 5623.13,7170.31 5647.53,7194.61 R1.1 5674.63,7222.81 5824.63,7372.81 5933.33,7372.81 5974.93,7372.81 6009.83,7407.71 6391.83,7407.71 6436.73,7362.81 6478.33,7362.81 6519.93,7362.81 6550.63,7393.61 6953.33,7393.61 LED4.1@6989.13,7357.81 ; 5623.13,6353.21 5695.43,6353.21 5775.83,6272.81 ; 5775.83,6272.81 5775.83,5670.91 6053.13,5393.61 ; 5826.43,4412.81 5826.43,5166.91 6053.13,5393.61 ; 5826.43,4412.81 5948.33,4412.81 5989.93,4412.81 5989.93,4468.31 6100.63,4579.01 6253.43,4579.01 6390.93,4441.51 6529.43,4441.51 6547.23,4423.71 ; 6053.13,5393.61 6102.83,5343.91 6102.83,5302.31 6428.63,5302.31 6465.23,5265.71 6562.83,5265.71 6562.83,5265.91 ; 6932.83,3414.71 U11.16 7127.53,3414.71
  Bottom Layer w10: H1.1@3941.13,6253.61 3983.33,6253.61 4270.13,5966.81 v1(4731.03,5966.81) 4731.03,5888.31 v1(4886.63,5732.71) ; R41.3 4841.23,4435.01 R32.3 ; C15.1 5376.73,4201.71 U5.1a ; U5.1b@5670.43,4104.81 5670.43,4180.41 v1(5680.33,4190.31) ; v1(5998.43,6336.91) v1(6418.93,6336.91) 6423.43,6341.41 v1(6962.03,6341.41) ; v1(6303.03,3341.91) v1(6932.83,3341.91) ; v1(6658.23,4534.71) 7584.93,4534.71 v1(7731.63,4387.91) ; v1(6863.43,5265.91) 6891.63,5294.11 v1(7117.53,5294.11) ; v2(7112.83,4342.81) 7228.53,4342.81 v1(7257.83,4313.51) 7300.83,4356.51 v1(7628.33,4356.51)
pads on no net: LED17.2 R5.2 R8.2 R9.2 R10.2 R11.2 R12.2 R13.2 R14.2 R15.2 R16.2 R17.2 R18.2 R19.2 R20.2 R21.2 R22.2 U1.4 U1.5 U1.6 U1.7 U1.8 U1.31 U1.32 U1.33 U1.34 U1.35 U1.36 U1.39 U1.40 U2.7 U2.10 U4.7 U4.8 U4.9 U4.10 U4.11 U4.12 U4.15 U5.9 U5.10 U7.9 U8.8 U8.9 U11.8 U11.9 U13.8 U13.9 U15.8 U15.9 USB2.1 USB2.2 USB2.3 USB2.4 USB2.A5 USB2.A8 USB2.B5 USB2.B8 USB3.1 USB3.2 USB3.3 USB3.4 USB3.A5 USB3.A8 USB3.B5 USB3.B8
copper on no net: | length 5376.1
  Top Layer w11.02: 6012.83,4007.81 6117.83,3902.81 6132.49,3902.81 6247.83,3787.47 ; 6087.83,5877.81 6088.17,5877.81 6353.17,5612.81 ; 6112.83,4802.81 6213.17,4802.81 6503.17,4512.81 ; 6202.83,6867.81 6323.17,6867.81 6488.17,6702.81 ; 6507.83,3967.81 6512.49,3967.81 6692.83,3787.47 ; 6612.83,5887.81 6633.17,5867.47 6633.17,5627.81 ; 6642.83,4772.81 6642.83,4688.15 6733.17,4597.81 ; 6677.83,6982.81 6698.17,6982.81 6863.17,6817.81 ; 6902.49,4597.81 7062.83,4758.15 7062.83,4837.81 ; 6927.49,3787.81 7157.83,4018.15 7157.83,4057.81 ; 7167.83,5947.81 7252.49,5863.15 7252.49,5632.81 ; 7217.83,6987.81 7272.49,6933.15 7272.49,6792.81 ; 7277.49,3777.81 7542.49,4042.81 7612.83,4042.81 ; 7367.49,4577.81 7522.83,4733.15 7522.83,4837.81 ; 7522.49,6682.81 7792.83,6953.15 7792.83,7012.81 ; 7572.49,5552.81 7572.49,5797.47 7657.83,5882.81

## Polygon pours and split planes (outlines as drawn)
GND on Bottom Layer (solid, remove dead copper, pour order 2): 3177.83,8502.81 3547.83,8132.81 9037.83,8132.81 9037.83,3202.81 8837.83,3002.81 3117.83,3002.81
GND on Top Layer (solid, remove dead copper, pour order 2): 3060,8500 3430,8130 8920,8130 8920,3200 8720,3000 3000,3000

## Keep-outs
Board Outline Layer:
  lines w10: 3887.83,7482.81 3887.83,3312.81 8082.83,3312.81 8082.83,7572.81 7812.04,7572.81 3891.78,7573.26 ; 3891.78,7443.24 3891.78,7578.26
Multi-Layer:
  circle w10: c7827.12,3656.59 r12.79
  circle w10: c7827.12,3429.03 r12.79
  circle w10: c7827.12,7486.59 r12.79
  circle w10: c7827.12,7259.03 r12.79

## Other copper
Top Layer:
  drawing of 483 lines, arcs and shapes, not listed
Bottom Layer:
  drawing of 142 lines, arcs and shapes, not listed

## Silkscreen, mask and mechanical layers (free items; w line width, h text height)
Top Silkscreen Layer:
  text "uva" at 7746.19,7411.16 h77.88 r90
  text "en" at 5034.65,7009 h76.56
  text "3" at 7237.83,6988.32 h75.94
  text "4" at 7717.83,6978.32 h75.94
  text "2" at 6602.83,6963.32 h75.94
  text "1" at 6022.83,6898.32 h75.94
  text "g" at 3957.83,6802.44 h75.94
  text "vcc" at 3835.78,6712.13 h76.56
  text "a1|x" at 3849.86,6617.13 h76.56
  text "i0" at 5059.65,6519 h76.56
  text "a2|y" at 3829.86,6507.13 h76.56
  text "i6" at 3866.7,6427.13 h76.56
  text "vcc" at 3970.78,6297.13 h76.56
  text "g" at 3977.83,6202.44 h75.94
  text "i8" at 3981.7,6082.13 h76.56
  text "i9" at 3976.7,5982.13 h76.56
  text "6" at 6582.83,5908.32 h75.94
  text "8" at 7622.83,5893.32 h75.94
  text "i10" at 3975.78,5882.13 h76.56
  text "7" at 7212.83,5868.32 h75.94
  text "5" at 6057.83,5848.32 h75.94
  text "i11" at 3975.78,5782.13 h76.56
  text "a2" at 4646.7,5462.13 h76.56
  text "i21" at 3981.2,5393.42 h76.56 r90
  text "i26" at 3981.64,5216.27 h76.56 r90
  text "i17" at 3981.2,5063.42 h76.56 r90
  text "a1" at 3936.7,4932.13 h76.56
  text "a3" at 4771.7,4907.13 h76.56
  text "10" at 6529.65,4834 h76.56
  text "9" at 6057.83,4803.32 h75.94
  text "12" at 7534.65,4799 h76.56
  text "11" at 7069.65,4764 h76.56
  text "13" at 5979.65,4039 h76.56
  text "15" at 7079.65,4014 h76.56
  text "16" at 7629.65,4004 h76.56
  text "14" at 6414.65,3994 h76.56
